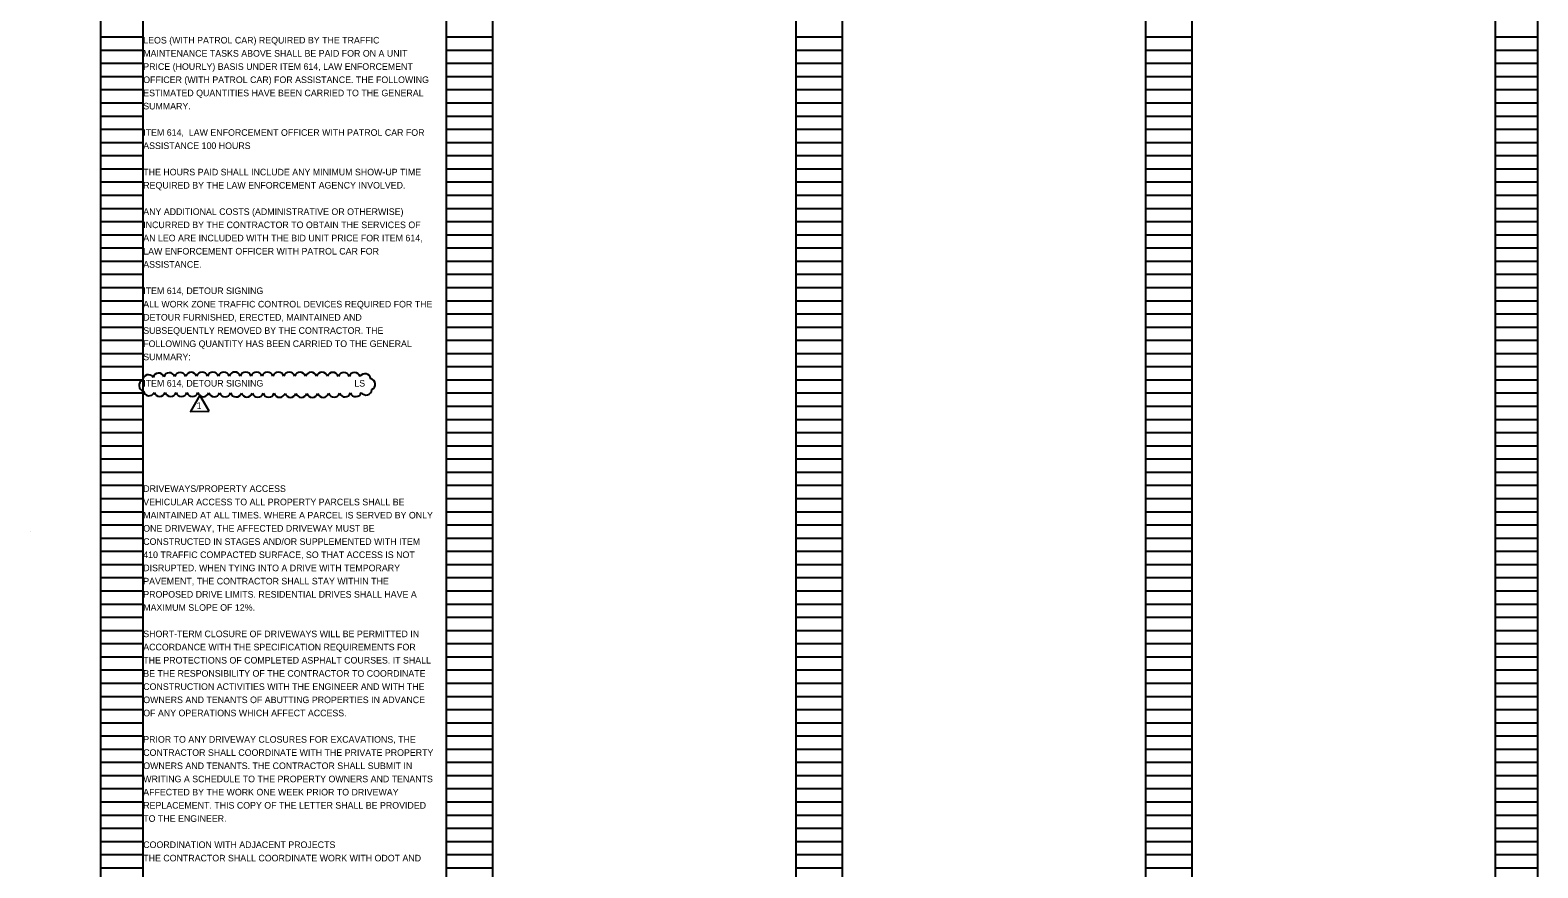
# Model space of a CAD drawing. Extents: x -9 to 32, y -122 to 20.
# Drawn here: x -0.28 to 31.72, y -68.3 to -50.51 of the extents above; entities that cross this region are included whole.
import ezdxf

# ---------------------------------------------------------------- set-up
doc = ezdxf.new("R2010")
doc.units = 0
for name, color, linetype in [('SC_Scratch1', 7, 'Continuous'), ('SC_Scratch2', 7, 'Continuous'), ('SH_Text', 7, 'Continuous')]:
    doc.layers.add(name, color=color, linetype=linetype)

msp = doc.modelspace()

# ---------------------------------------------------------------- linework, layer by layer
at = {"layer": 'SC_Scratch1'}
for p, q in [((1.216, -60.174), (1.216, -40.014)), ((2.116, -60.174), (2.116, -40.014)), ((8.556, -60.174), (8.556, -40.014)), ((9.536, -60.174), (9.536, -40.014)), ((15.976, -60.174), (15.976, -40.014)), ((16.956, -60.174), (16.956, -40.014)), ((23.396, -60.174), (23.396, -40.014)), ((24.376, -60.174), (24.376, -40.014)), ((30.816, -60.174), (30.816, -40.014)), ((31.716, -60.174), (31.716, -40.014)), ((1.216, -50.654), (2.116, -50.654)), ((8.556, -50.654), (9.536, -50.654)), ((15.976, -50.654), (16.956, -50.654)), ((23.396, -50.654), (24.376, -50.654)), ((30.816, -50.654), (31.716, -50.654)), ((1.216, -50.934), (2.116, -50.934)), ((8.556, -50.934), (9.536, -50.934)), ((15.976, -50.934), (16.956, -50.934)), ((23.396, -50.934), (24.376, -50.934)), ((30.816, -50.934), (31.716, -50.934)), ((1.216, -51.214), (2.116, -51.214)), ((1.216, -51.494), (2.116, -51.494)), ((8.556, -51.214), (9.536, -51.214)), ((8.556, -51.494), (9.536, -51.494)), ((15.976, -51.214), (16.956, -51.214)), ((15.976, -51.494), (16.956, -51.494)), ((23.396, -51.214), (24.376, -51.214)), ((23.396, -51.494), (24.376, -51.494)), ((30.816, -51.214), (31.716, -51.214)), ((30.816, -51.494), (31.716, -51.494)), ((1.216, -51.774), (2.116, -51.774)), ((8.556, -51.774), (9.536, -51.774)), ((15.976, -51.774), (16.956, -51.774)), ((23.396, -51.774), (24.376, -51.774)), ((30.816, -51.774), (31.716, -51.774)), ((1.216, -52.054), (2.116, -52.054)), ((8.556, -52.054), (9.536, -52.054)), ((15.976, -52.054), (16.956, -52.054)), ((23.396, -52.054), (24.376, -52.054)), ((30.816, -52.054), (31.716, -52.054)), ((1.216, -52.334), (2.116, -52.334)), ((8.556, -52.334), (9.536, -52.334)), ((15.976, -52.334), (16.956, -52.334)), ((23.396, -52.334), (24.376, -52.334)), ((30.816, -52.334), (31.716, -52.334)), ((1.216, -52.614), (2.116, -52.614)), ((8.556, -52.614), (9.536, -52.614)), ((15.976, -52.614), (16.956, -52.614)), ((23.396, -52.614), (24.376, -52.614)), ((30.816, -52.614), (31.716, -52.614)), ((1.216, -52.894), (2.116, -52.894)), ((8.556, -52.894), (9.536, -52.894)), ((15.976, -52.894), (16.956, -52.894)), ((23.396, -52.894), (24.376, -52.894)), ((30.816, -52.894), (31.716, -52.894)), ((1.216, -53.174), (2.116, -53.174)), ((8.556, -53.174), (9.536, -53.174)), ((15.976, -53.174), (16.956, -53.174)), ((23.396, -53.174), (24.376, -53.174)), ((30.816, -53.174), (31.716, -53.174)), ((1.216, -53.454), (2.116, -53.454)), ((1.216, -53.734), (2.116, -53.734)), ((8.556, -53.454), (9.536, -53.454)), ((8.556, -53.734), (9.536, -53.734)), ((15.976, -53.454), (16.956, -53.454)), ((15.976, -53.734), (16.956, -53.734)), ((23.396, -53.454), (24.376, -53.454)), ((23.396, -53.734), (24.376, -53.734)), ((30.816, -53.454), (31.716, -53.454)), ((30.816, -53.734), (31.716, -53.734)), ((1.216, -54.014), (2.116, -54.014)), ((8.556, -54.014), (9.536, -54.014)), ((15.976, -54.014), (16.956, -54.014)), ((23.396, -54.014), (24.376, -54.014)), ((30.816, -54.014), (31.716, -54.014)), ((1.216, -54.294), (2.116, -54.294)), ((8.556, -54.294), (9.536, -54.294)), ((15.976, -54.294), (16.956, -54.294)), ((23.396, -54.294), (24.376, -54.294)), ((30.816, -54.294), (31.716, -54.294)), ((1.216, -54.574), (2.116, -54.574)), ((8.556, -54.574), (9.536, -54.574)), ((15.976, -54.574), (16.956, -54.574)), ((23.396, -54.574), (24.376, -54.574)), ((30.816, -54.574), (31.716, -54.574)), ((1.216, -54.854), (2.116, -54.854)), ((8.556, -54.854), (9.536, -54.854)), ((15.976, -54.854), (16.956, -54.854)), ((23.396, -54.854), (24.376, -54.854)), ((30.816, -54.854), (31.716, -54.854)), ((1.216, -55.134), (2.116, -55.134)), ((8.556, -55.134), (9.536, -55.134)), ((15.976, -55.134), (16.956, -55.134)), ((23.396, -55.134), (24.376, -55.134)), ((30.816, -55.134), (31.716, -55.134)), ((1.216, -55.414), (2.116, -55.414)), ((8.556, -55.414), (9.536, -55.414)), ((15.976, -55.414), (16.956, -55.414)), ((23.396, -55.414), (24.376, -55.414)), ((30.816, -55.414), (31.716, -55.414)), ((1.216, -55.694), (2.116, -55.694)), ((1.216, -55.974), (2.116, -55.974)), ((8.556, -55.694), (9.536, -55.694)), ((8.556, -55.974), (9.536, -55.974)), ((15.976, -55.694), (16.956, -55.694)), ((15.976, -55.974), (16.956, -55.974)), ((23.396, -55.694), (24.376, -55.694)), ((23.396, -55.974), (24.376, -55.974)), ((30.816, -55.694), (31.716, -55.694)), ((30.816, -55.974), (31.716, -55.974)), ((1.216, -56.254), (2.116, -56.254)), ((8.556, -56.254), (9.536, -56.254)), ((15.976, -56.254), (16.956, -56.254)), ((23.396, -56.254), (24.376, -56.254)), ((30.816, -56.254), (31.716, -56.254)), ((1.216, -56.534), (2.116, -56.534)), ((8.556, -56.534), (9.536, -56.534)), ((15.976, -56.534), (16.956, -56.534)), ((23.396, -56.534), (24.376, -56.534)), ((30.816, -56.534), (31.716, -56.534)), ((1.216, -56.814), (2.116, -56.814)), ((8.556, -56.814), (9.536, -56.814)), ((15.976, -56.814), (16.956, -56.814)), ((23.396, -56.814), (24.376, -56.814)), ((30.816, -56.814), (31.716, -56.814)), ((1.216, -57.094), (2.116, -57.094)), ((8.556, -57.094), (9.536, -57.094)), ((15.976, -57.094), (16.956, -57.094)), ((23.396, -57.094), (24.376, -57.094)), ((30.816, -57.094), (31.716, -57.094)), ((1.216, -57.374), (2.116, -57.374)), ((8.556, -57.374), (9.536, -57.374)), ((15.976, -57.374), (16.956, -57.374)), ((23.396, -57.374), (24.376, -57.374)), ((30.816, -57.374), (31.716, -57.374)), ((1.216, -57.654), (2.116, -57.654)), ((8.556, -57.654), (9.536, -57.654)), ((15.976, -57.654), (16.956, -57.654)), ((23.396, -57.654), (24.376, -57.654)), ((30.816, -57.654), (31.716, -57.654)), ((1.216, -57.934), (2.116, -57.934)), ((1.216, -58.214), (2.116, -58.214)), ((8.556, -57.934), (9.536, -57.934)), ((8.556, -58.214), (9.536, -58.214)), ((15.976, -57.934), (16.956, -57.934)), ((15.976, -58.214), (16.956, -58.214)), ((23.396, -57.934), (24.376, -57.934)), ((23.396, -58.214), (24.376, -58.214)), ((30.816, -57.934), (31.716, -57.934)), ((30.816, -58.214), (31.716, -58.214)), ((1.216, -58.494), (2.116, -58.494)), ((8.556, -58.494), (9.536, -58.494)), ((15.976, -58.494), (16.956, -58.494)), ((23.396, -58.494), (24.376, -58.494)), ((30.816, -58.494), (31.716, -58.494)), ((1.216, -58.774), (2.116, -58.774)), ((8.556, -58.774), (9.536, -58.774)), ((15.976, -58.774), (16.956, -58.774)), ((23.396, -58.774), (24.376, -58.774)), ((30.816, -58.774), (31.716, -58.774)), ((1.216, -59.054), (2.116, -59.054)), ((8.556, -59.054), (9.536, -59.054)), ((15.976, -59.054), (16.956, -59.054)), ((23.396, -59.054), (24.376, -59.054)), ((30.816, -59.054), (31.716, -59.054)), ((1.216, -59.334), (2.116, -59.334)), ((8.556, -59.334), (9.536, -59.334)), ((15.976, -59.334), (16.956, -59.334)), ((23.396, -59.334), (24.376, -59.334)), ((30.816, -59.334), (31.716, -59.334)), ((1.216, -59.614), (2.116, -59.614)), ((8.556, -59.614), (9.536, -59.614)), ((15.976, -59.614), (16.956, -59.614)), ((23.396, -59.614), (24.376, -59.614)), ((30.816, -59.614), (31.716, -59.614)), ((1.216, -59.894), (2.116, -59.894)), ((8.556, -59.894), (9.536, -59.894)), ((15.976, -59.894), (16.956, -59.894)), ((23.396, -59.894), (24.376, -59.894)), ((30.816, -59.894), (31.716, -59.894)), ((1.216, -60.174), (2.116, -60.174)), ((1.216, -80.334), (1.216, -60.174)), ((1.216, -60.174), (2.116, -60.174)), ((1.216, -60.454), (2.116, -60.454)), ((2.116, -80.334), (2.116, -60.174)), ((8.556, -60.174), (9.536, -60.174)), ((8.556, -80.334), (8.556, -60.174)), ((8.556, -60.174), (9.536, -60.174)), ((8.556, -60.454), (9.536, -60.454)), ((9.536, -80.334), (9.536, -60.174)), ((15.976, -60.174), (16.956, -60.174)), ((15.976, -80.334), (15.976, -60.174)), ((15.976, -60.174), (16.956, -60.174)), ((15.976, -60.454), (16.956, -60.454)), ((16.956, -80.334), (16.956, -60.174)), ((23.396, -60.174), (24.376, -60.174)), ((23.396, -80.334), (23.396, -60.174)), ((23.396, -60.174), (24.376, -60.174)), ((23.396, -60.454), (24.376, -60.454)), ((24.376, -80.334), (24.376, -60.174)), ((30.816, -60.174), (31.716, -60.174)), ((30.816, -80.334), (30.816, -60.174)), ((30.816, -60.174), (31.716, -60.174)), ((30.816, -60.454), (31.716, -60.454)), ((31.716, -80.334), (31.716, -60.174)), ((1.216, -60.734), (2.116, -60.734)), ((8.556, -60.734), (9.536, -60.734)), ((15.976, -60.734), (16.956, -60.734)), ((23.396, -60.734), (24.376, -60.734)), ((30.816, -60.734), (31.716, -60.734)), ((1.216, -61.014), (2.116, -61.014)), ((8.556, -61.014), (9.536, -61.014)), ((15.976, -61.014), (16.956, -61.014)), ((23.396, -61.014), (24.376, -61.014)), ((30.816, -61.014), (31.716, -61.014)), ((-0.284, -61.154), (-0.284, -61.154)), ((1.216, -61.294), (2.116, -61.294)), ((8.556, -61.294), (9.536, -61.294)), ((15.976, -61.294), (16.956, -61.294)), ((23.396, -61.294), (24.376, -61.294)), ((30.816, -61.294), (31.716, -61.294)), ((1.216, -61.574), (2.116, -61.574)), ((8.556, -61.574), (9.536, -61.574)), ((15.976, -61.574), (16.956, -61.574)), ((23.396, -61.574), (24.376, -61.574)), ((30.816, -61.574), (31.716, -61.574)), ((1.216, -61.854), (2.116, -61.854)), ((8.556, -61.854), (9.536, -61.854)), ((15.976, -61.854), (16.956, -61.854)), ((23.396, -61.854), (24.376, -61.854)), ((30.816, -61.854), (31.716, -61.854)), ((1.216, -62.134), (2.116, -62.134)), ((8.556, -62.134), (9.536, -62.134)), ((15.976, -62.134), (16.956, -62.134)), ((23.396, -62.134), (24.376, -62.134)), ((30.816, -62.134), (31.716, -62.134)), ((1.216, -62.414), (2.116, -62.414)), ((1.216, -62.694), (2.116, -62.694)), ((8.556, -62.414), (9.536, -62.414)), ((8.556, -62.694), (9.536, -62.694)), ((15.976, -62.414), (16.956, -62.414)), ((15.976, -62.694), (16.956, -62.694)), ((23.396, -62.414), (24.376, -62.414)), ((23.396, -62.694), (24.376, -62.694)), ((30.816, -62.414), (31.716, -62.414)), ((30.816, -62.694), (31.716, -62.694)), ((1.216, -62.974), (2.116, -62.974)), ((8.556, -62.974), (9.536, -62.974)), ((15.976, -62.974), (16.956, -62.974)), ((23.396, -62.974), (24.376, -62.974)), ((30.816, -62.974), (31.716, -62.974)), ((1.216, -63.254), (2.116, -63.254)), ((8.556, -63.254), (9.536, -63.254)), ((15.976, -63.254), (16.956, -63.254)), ((23.396, -63.254), (24.376, -63.254)), ((30.816, -63.254), (31.716, -63.254)), ((1.216, -63.534), (2.116, -63.534)), ((8.556, -63.534), (9.536, -63.534)), ((15.976, -63.534), (16.956, -63.534)), ((23.396, -63.534), (24.376, -63.534)), ((30.816, -63.534), (31.716, -63.534)), ((1.216, -63.814), (2.116, -63.814)), ((8.556, -63.814), (9.536, -63.814)), ((15.976, -63.814), (16.956, -63.814)), ((23.396, -63.814), (24.376, -63.814)), ((30.816, -63.814), (31.716, -63.814)), ((1.216, -64.094), (2.116, -64.094)), ((8.556, -64.094), (9.536, -64.094)), ((15.976, -64.094), (16.956, -64.094)), ((23.396, -64.094), (24.376, -64.094)), ((30.816, -64.094), (31.716, -64.094)), ((1.216, -64.374), (2.116, -64.374)), ((8.556, -64.374), (9.536, -64.374)), ((15.976, -64.374), (16.956, -64.374)), ((23.396, -64.374), (24.376, -64.374)), ((30.816, -64.374), (31.716, -64.374)), ((1.216, -64.654), (2.116, -64.654)), ((1.216, -64.934), (2.116, -64.934)), ((8.556, -64.654), (9.536, -64.654)), ((8.556, -64.934), (9.536, -64.934)), ((15.976, -64.654), (16.956, -64.654)), ((15.976, -64.934), (16.956, -64.934)), ((23.396, -64.654), (24.376, -64.654)), ((23.396, -64.934), (24.376, -64.934)), ((30.816, -64.654), (31.716, -64.654)), ((30.816, -64.934), (31.716, -64.934)), ((1.216, -65.214), (2.116, -65.214)), ((8.556, -65.214), (9.536, -65.214)), ((15.976, -65.214), (16.956, -65.214)), ((23.396, -65.214), (24.376, -65.214)), ((30.816, -65.214), (31.716, -65.214)), ((1.216, -65.494), (2.116, -65.494)), ((8.556, -65.494), (9.536, -65.494)), ((15.976, -65.494), (16.956, -65.494)), ((23.396, -65.494), (24.376, -65.494)), ((30.816, -65.494), (31.716, -65.494)), ((1.216, -65.774), (2.116, -65.774)), ((8.556, -65.774), (9.536, -65.774)), ((15.976, -65.774), (16.956, -65.774)), ((23.396, -65.774), (24.376, -65.774)), ((30.816, -65.774), (31.716, -65.774)), ((1.216, -66.054), (2.116, -66.054)), ((8.556, -66.054), (9.536, -66.054)), ((15.976, -66.054), (16.956, -66.054)), ((23.396, -66.054), (24.376, -66.054)), ((30.816, -66.054), (31.716, -66.054)), ((1.216, -66.334), (2.116, -66.334)), ((8.556, -66.334), (9.536, -66.334)), ((15.976, -66.334), (16.956, -66.334)), ((23.396, -66.334), (24.376, -66.334)), ((30.816, -66.334), (31.716, -66.334)), ((1.216, -66.614), (2.116, -66.614)), ((8.556, -66.614), (9.536, -66.614)), ((15.976, -66.614), (16.956, -66.614)), ((23.396, -66.614), (24.376, -66.614)), ((30.816, -66.614), (31.716, -66.614)), ((1.216, -66.894), (2.116, -66.894)), ((1.216, -67.174), (2.116, -67.174)), ((8.556, -66.894), (9.536, -66.894)), ((8.556, -67.174), (9.536, -67.174)), ((15.976, -66.894), (16.956, -66.894)), ((15.976, -67.174), (16.956, -67.174)), ((23.396, -66.894), (24.376, -66.894)), ((23.396, -67.174), (24.376, -67.174)), ((30.816, -66.894), (31.716, -66.894)), ((30.816, -67.174), (31.716, -67.174)), ((1.216, -67.454), (2.116, -67.454)), ((8.556, -67.454), (9.536, -67.454)), ((15.976, -67.454), (16.956, -67.454)), ((23.396, -67.454), (24.376, -67.454)), ((30.816, -67.454), (31.716, -67.454)), ((1.216, -67.734), (2.116, -67.734)), ((8.556, -67.734), (9.536, -67.734)), ((15.976, -67.734), (16.956, -67.734)), ((23.396, -67.734), (24.376, -67.734)), ((30.816, -67.734), (31.716, -67.734)), ((1.216, -68.014), (2.116, -68.014)), ((8.556, -68.014), (9.536, -68.014)), ((15.976, -68.014), (16.956, -68.014)), ((23.396, -68.014), (24.376, -68.014)), ((30.816, -68.014), (31.716, -68.014)), ((1.216, -68.294), (2.116, -68.294)), ((8.556, -68.294), (9.536, -68.294)), ((15.976, -68.294), (16.956, -68.294)), ((23.396, -68.294), (24.376, -68.294)), ((30.816, -68.294), (31.716, -68.294))]:
    msp.add_line(p, q, dxfattribs=at)
at = {"layer": 'SC_Scratch2'}
msp.add_lwpolyline([(3.518, -58.6), (3.314, -58.258), (3.12, -58.606)], close=True, dxfattribs=at)
for centre, start, end in [((2.222, -57.947), 32.6895, 177.6895), ((2.441, -57.913), 20.2814, 165.2814), ((2.671, -57.904), 19.0988, 164.0988), ((2.902, -57.899), 18.5339, 163.5339), ((3.134, -57.895), 18.1848, 163.1848), ((3.365, -57.893), 17.9415, 162.9415), ((3.596, -57.891), 17.7593, 162.7593), ((3.827, -57.891), 17.6163, 162.6163), ((4.058, -57.89), 17.5002, 162.5002), ((4.29, -57.891), 17.4035, 162.4035), ((4.521, -57.891), 17.3315, 162.3315), ((4.752, -57.892), 17.3153, 162.3153), ((4.984, -57.893), 17.3042, 162.3042), ((5.215, -57.893), 17.2909, 162.2909), ((5.446, -57.894), 17.2744, 162.2744), ((5.678, -57.895), 17.2533, 162.2533), ((5.909, -57.896), 17.2248, 162.2248), ((6.14, -57.897), 17.1834, 162.1834), ((6.372, -57.899), 17.1145, 162.1145), ((6.603, -57.901), 16.9594, 161.9594), ((6.825, -57.924), 5.8666, 150.8666), ((6.921, -58.031), 293.2925, 78.2925), ((2.147, -58.055), 112.3977, 257.3977), ((2.24, -58.151), 190.2839, 335.2839), ((2.465, -58.165), 197.5096, 342.5096), ((2.697, -58.166), 197.1687, 342.1687), ((2.928, -58.168), 197.0952, 342.0952), ((3.16, -58.169), 197.0568, 342.0568), ((3.391, -58.171), 197.0321, 342.0321), ((3.622, -58.173), 197.0146, 342.0146), ((3.854, -58.175), 197.0013, 342.0013), ((4.085, -58.177), 196.9908, 341.9908), ((4.316, -58.179), 196.9821, 341.9821), ((4.548, -58.181), 196.9749, 341.9749), ((4.779, -58.183), 197.0078, 342.0078), ((5.01, -58.185), 197.1222, 342.1222), ((5.242, -58.186), 197.2607, 342.2607), ((5.473, -58.187), 197.4305, 342.4305), ((5.704, -58.187), 197.6454, 342.6454), ((5.935, -58.186), 197.93, 342.93), ((6.166, -58.183), 198.3326, 343.3326), ((6.397, -58.178), 198.9678, 343.9678), ((6.627, -58.17), 200.2178, 345.2178), ((6.847, -58.136), 212.2563, 357.2563)]:
    msp.add_arc(centre, 0.121, start, end, dxfattribs=at)

# ---------------------------------------------------------------- texts
msp.add_text('1', height=0.14, dxfattribs=at).set_placement((3.249, -58.552))
at = {"layer": 'SH_Text'}
for s, p in [('LEOS (WITH PATROL CAR) REQUIRED BY THE TRAFFIC ', (2.116, -50.794)), ('MAINTENANCE TASKS ABOVE SHALL BE PAID FOR ON A UNIT ', (2.116, -51.074)), ('OFFICER (WITH PATROL CAR) FOR ASSISTANCE. THE FOLLOWING ', (2.116, -51.634)), ('PRICE (HOURLY) BASIS UNDER ITEM 614, LAW ENFORCEMENT ', (2.116, -51.354)), ('ESTIMATED QUANTITIES HAVE BEEN CARRIED TO THE GENERAL ', (2.116, -51.914)), ('SUMMARY.', (2.116, -52.194)), ('ITEM 614,  LAW ENFORCEMENT OFFICER WITH PATROL CAR FOR ', (2.116, -52.754)), ('ASSISTANCE 100 HOURS', (2.116, -53.034)), ('THE HOURS PAID SHALL INCLUDE ANY MINIMUM SHOW-UP TIME ', (2.116, -53.594)), ('REQUIRED BY THE LAW ENFORCEMENT AGENCY INVOLVED.', (2.116, -53.874)), ('ANY ADDITIONAL COSTS (ADMINISTRATIVE OR OTHERWISE) ', (2.116, -54.434)), ('INCURRED BY THE CONTRACTOR TO OBTAIN THE SERVICES OF ', (2.116, -54.714)), ('AN LEO ARE INCLUDED WITH THE BID UNIT PRICE FOR ITEM 614, ', (2.116, -54.994)), ('LAW ENFORCEMENT OFFICER WITH PATROL CAR FOR ', (2.116, -55.274)), ('ASSISTANCE.', (2.116, -55.554)), ('ITEM 614, DETOUR SIGNING', (2.116, -56.114)), ('ALL WORK ZONE TRAFFIC CONTROL DEVICES REQUIRED FOR THE ', (2.116, -56.398)), ('DETOUR FURNISHED, ERECTED, MAINTAINED AND ', (2.116, -56.678)), ('SUBSEQUENTLY REMOVED BY THE CONTRACTOR. THE ', (2.116, -56.958)), ('FOLLOWING QUANTITY HAS BEEN CARRIED TO THE GENERAL ', (2.116, -57.238)), ('SUMMARY:', (2.116, -57.518)), ('ITEM 614, DETOUR SIGNING', (2.116, -58.078)), ('LS', (6.596, -58.078)), ('VEHICULAR ACCESS TO ALL PROPERTY PARCELS SHALL BE ', (2.116, -60.598)), ('DRIVEWAYS/PROPERTY ACCESS', (2.116, -60.314)), ('MAINTAINED AT ALL TIMES. WHERE A PARCEL IS SERVED BY ONLY ', (2.116, -60.878)), ('ONE DRIVEWAY, THE AFFECTED DRIVEWAY MUST BE ', (2.116, -61.158)), ('CONSTRUCTED IN STAGES AND/OR SUPPLEMENTED WITH ITEM ', (2.116, -61.438)), ('410 TRAFFIC COMPACTED SURFACE, SO THAT ACCESS IS NOT ', (2.116, -61.718)), ('DISRUPTED. WHEN TYING INTO A DRIVE WITH TEMPORARY ', (2.116, -61.998)), ('PAVEMENT, THE CONTRACTOR SHALL STAY WITHIN THE ', (2.116, -62.278)), ('PROPOSED DRIVE LIMITS. RESIDENTIAL DRIVES SHALL HAVE A ', (2.116, -62.558)), ('MAXIMUM SLOPE OF 12%.', (2.116, -62.838)), ('SHORT-TERM CLOSURE OF DRIVEWAYS WILL BE PERMITTED IN ', (2.116, -63.398)), ('ACCORDANCE WITH THE SPECIFICATION REQUIREMENTS FOR ', (2.116, -63.678)), ('THE PROTECTIONS OF COMPLETED ASPHALT COURSES. IT SHALL ', (2.116, -63.958)), ('BE THE RESPONSIBILITY OF THE CONTRACTOR TO COORDINATE ', (2.116, -64.238)), ('CONSTRUCTION ACTIVITIES WITH THE ENGINEER AND WITH THE ', (2.116, -64.518)), ('OWNERS AND TENANTS OF ABUTTING PROPERTIES IN ADVANCE ', (2.116, -64.798)), ('OF ANY OPERATIONS WHICH AFFECT ACCESS.', (2.116, -65.078)), ('PRIOR TO ANY DRIVEWAY CLOSURES FOR EXCAVATIONS, THE ', (2.116, -65.638)), ('CONTRACTOR SHALL COORDINATE WITH THE PRIVATE PROPERTY ', (2.116, -65.918)), ('OWNERS AND TENANTS. THE CONTRACTOR SHALL SUBMIT IN ', (2.116, -66.198)), ('WRITING A SCHEDULE TO THE PROPERTY OWNERS AND TENANTS ', (2.116, -66.478)), ('AFFECTED BY THE WORK ONE WEEK PRIOR TO DRIVEWAY ', (2.116, -66.758)), ('TO THE ENGINEER. ', (2.116, -67.318)), ('REPLACEMENT. THIS COPY OF THE LETTER SHALL BE PROVIDED ', (2.116, -67.038)), ('COORDINATION WITH ADJACENT PROJECTS', (2.116, -67.874)), ('THE CONTRACTOR SHALL COORDINATE WORK WITH ODOT AND ', (2.116, -68.158))]:
    msp.add_text(s, height=0.14, dxfattribs=at).set_placement(p)

doc.saveas('drawing.dxf')
